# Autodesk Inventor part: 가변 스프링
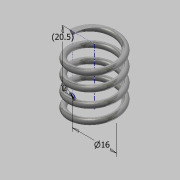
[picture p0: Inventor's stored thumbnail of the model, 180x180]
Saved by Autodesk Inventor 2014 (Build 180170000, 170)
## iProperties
Created: 2015-04
Part Number: 가변 스프링
Material: 강철, 탄소
Document SubType Name: Modeling
Designer: Administrator
Density: 7.87 g/cm^3
Appearance: 반연마
Mass: 4.86823 g
Surface Area: 12.612 cm^2
Volume: 0.618581 cm^3
Author: Administrator
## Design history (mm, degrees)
sketch "스케치4"
  geometry: L1 (0, 0)-(8, 0); L2 (8, 0)-(8, 20.5); L3 (8, 20.5)-(0, 20.5); L4 (0, 20.5)-(0, 0); C1 r 1 at (8, 0)
  constraints: 8 end point, 2 parallel, 1 centre point, 1 coincident, 1 horizontal, 1 perpendicular
  dimensions: "d0" = 16 diameter of L2 L4; "d1" = 20.49951 distance between parallel lines of L3 L1 (derived); "d2" = 2 diameter of C1
feature "코일1" pitch "d3" = 10; turns "d5" = 4; dims "d4" = 20.49951 (= d1), "d6" = 0, angle "d7" = 90 deg, angle "d8" = 90 deg, "d9" = 0, "d10" = 0
node "작업 평면1"
sketch "스케치5"
  geometry: L1 (7, 0)-(9, 0) reference; 1 further point
  constraints: 1 horizontal alignment
extrude "돌출1" cut sketch "스케치5" stored distance "d11" = 10; taper "d12" = 0 deg
node "작업 평면2"
sketch "스케치6"
  geometry: L1 (9, 0)-(7, 0) reference; 1 further point
  constraints: 1 horizontal alignment
extrude "돌출2" cut sketch "스케치6" stored distance "d13" = 10; taper "d14" = 0 deg
node "솔리드1"
node "절단 모서리 투영1"
node "절단 모서리 투영2"
